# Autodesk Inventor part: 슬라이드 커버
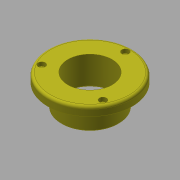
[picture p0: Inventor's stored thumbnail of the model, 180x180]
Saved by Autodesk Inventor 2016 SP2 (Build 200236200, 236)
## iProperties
Created: 2015-10
Part Number: 슬라이드 커버
Document SubType Name: Modeling
Designer: mdu
Density: 7.86 g/cm^3
Material: 강철, 연강
Mass: 635.45 g
Surface Area: 238.05 cm^2
Volume: 80.8461 cm^3
Appearance: 밝은 황색
Author: mdu
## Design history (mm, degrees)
sketch "스케치1"
  geometry: C1 r 47.5 at (0, 0); C2 r 32.5 at (0, 0); 1 further point
  constraints: 2 centre point, 2 coincident
  dimensions: "d33" = 95 diameter of C1; "d35" = 65 diameter of C2
extrude "돌출1" new body sketch "스케치1" distance "d0" = 10; taper "d1" = 0 deg
extrude "돌출2" join sketch "스케치1" distance "d2" = 25; taper "d3" = 0 deg
hole "구멍1" diameter "d6" = 50; stored, may be unused: countersink angle "d10" = 90 deg, drill point angle "d12" = 118 deg; dims "d4" = 10, "d5" = 10, "d7" = 6, "d8" = 4, "d9" = 2, "d11" = 8
sketch "스케치2" dims "d36" = 80
  geometry: 4 further points
  constraints: 2 coincident, 2 vertical alignment, 2 other
hole "구멍2" sketch "스케치2" at (0, 40) diameter "d13" = 4.5; stored, may be unused: countersink angle "d17" = 90 deg, drill point angle "d19" = 118 deg; dims "d14" = 6, "d15" = 8, "d16" = 4.4, "d18" = 8
fillet "모깎기1" dims "d23" = 3
chamfer "모따기1" distance "d24" = 1; stored, may be unused: second distance "d25" = 2, angle "d26" = 45 deg
sketch "스케치3"
  geometry: C1 r 25 at (0, 0); C2 r 30 at (0, 0); C3 r 26 at (0, 0) reference; 1 further point
  constraints: 2 centre point, 2 coincident
  dimensions: "d27" = 60 diameter of C2
extrude "돌출3" cut sketch "스케치3" distance "d28" = 3; taper "d29" = 0 deg
chamfer "모따기2" distance "d30" = 1; stored, may be unused: second distance "d31" = 2, angle "d32" = 45 deg
node "솔리드1"
pattern_circular "원형 패턴1" dims angle "d21" = 360 deg
